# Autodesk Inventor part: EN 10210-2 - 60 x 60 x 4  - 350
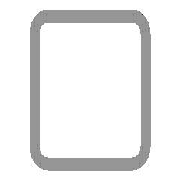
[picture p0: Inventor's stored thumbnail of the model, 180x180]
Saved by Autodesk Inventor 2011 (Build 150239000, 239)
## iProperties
_CCFamilyMember: 20
_CCFamilyDisplayName: DIN EN 10219-2 (Square Hollow Section - Cold Formed) - Cold formed welded structural hollow sections of non-alloy and fine grain structural steel
_FrameMemberDoc: Frame Member File
_Version: 15.0.0
_GetPNFromCC: 1
IsCustomPart: 1
Created: 2010-02
Part Number: EN 10210-2 - 60 x 60 x 4  - 350
Material: Steel, Mild
Description: Tube 60*60*4
Document SubType Name: Modeling
Standard: DIN
Designer: PC
Standard Revision: 1997
Standards Organization: DIN
Language: en-US
Size Designation: 60 x 60 x 4
Categories: <MemberInstance><Categories><Category DisplayName="Structural Shapes" InternalName="089c4875-fa83-4c05-b084-43b9cc11f5ed" Mnemonic="GRDR"><CategoryParameter Dis
Stock Number: 60 x 60 x 4
Density: 7.86 g/cm^3
G_L: 350.000 mm
G_W: 60.000 mm
G_H: 60.000 mm
Author: PC
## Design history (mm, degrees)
node "Start plane"
node "End plane"
sketch "Sketch"
  geometry: L1 (-30, -22)-(-30, 22); L2 (-22, 30)-(22, 30); L3 (30, 22)-(30, -22); L4 (22, -30)-(-22, -30); L5 (-22, 26)-(22, 26); L6 (26, 22)-(26, -22); L7 (22, -26)-(-22, -26); L8 (-26, -22)-(-26, 22); L9 (0, 44.32)-(0, -44.32) reference; L10 (-44.32, 0)-(44.32, 0) reference; A1 r 8 centre (-22, -22) between (-30, -22) and (-22, -30); A2 r 8 centre (-22, 22) between (-22, 30) and (-30, 22); A3 r 8 centre (22, 22) between (30, 22) and (22, 30); A4 r 8 centre (22, -22) between (22, -30) and (30, -22); A5 r 4 centre (-22, 22) between (-22, 26) and (-26, 22); A6 r 4 centre (22, 22) between (26, 22) and (22, 26); A7 r 4 centre (22, -22) between (22, -26) and (26, -22); A8 r 4 centre (-22, -22) between (-26, -22) and (-22, -26)
  constraints: 16 end point, 16 point on circle, 8 centre point, 8 tangent, 4 parallel, 3 equal radius, 2 perpendicular, 7 other
  dimensions: "d7" = 8 radius of A1 (= G_IR); "d10" = 60 distance between parallel lines of L2 L4 (= G_H); "d11" = 60 distance between parallel lines of L1 L3 (= G_W); "d12" = 4 distance between parallel lines of L3 L6 (= G_T); "d15" = 30 distance between parallel lines of L2 L10 (= 0.5 x d10); "d16" = 30 distance between parallel lines of L9 L3 (= 0.5 x d11)
extrude "Body" new body sketch "Sketch" stored distance "d3" = 350 (= G_L); taper "d4" = 0 deg
node "Driven Length"
  sketch "Sketch3"
    geometry: L1 (0, 0)-(10, 0) reference
    constraints: 2 end point, 1 horizontal
  workplane "Work Plane3"
  sketch "Sketch4"
    geometry: L1 (-2, 0)-(12, 0) reference; L2 (-2, 350)-(12, 350) reference
    dimensions: "d18" = 350 distance between parallel lines of L1 L2 (derived)
body "Solid1"
other parameters: "G_W" = 60 [user parameter; used in 1 equation term], "G_H" = 60 [user parameter; used in 1 equation term], "G_T" = 4 [user parameter; used in 1 equation term], "G_IR" = 8 [user parameter; used in 1 equation term], "G_L" = 350 (= d18) [user parameter; used in 1 equation term], "G_OFFSET_START" = 0 [user parameter; used in 1 equation term], "G_OFFSET_END" = 0 [user parameter; used in 1 equation term], "d13" = 0 (computed from G_OFFSET_START), "d17" = 90 deg
